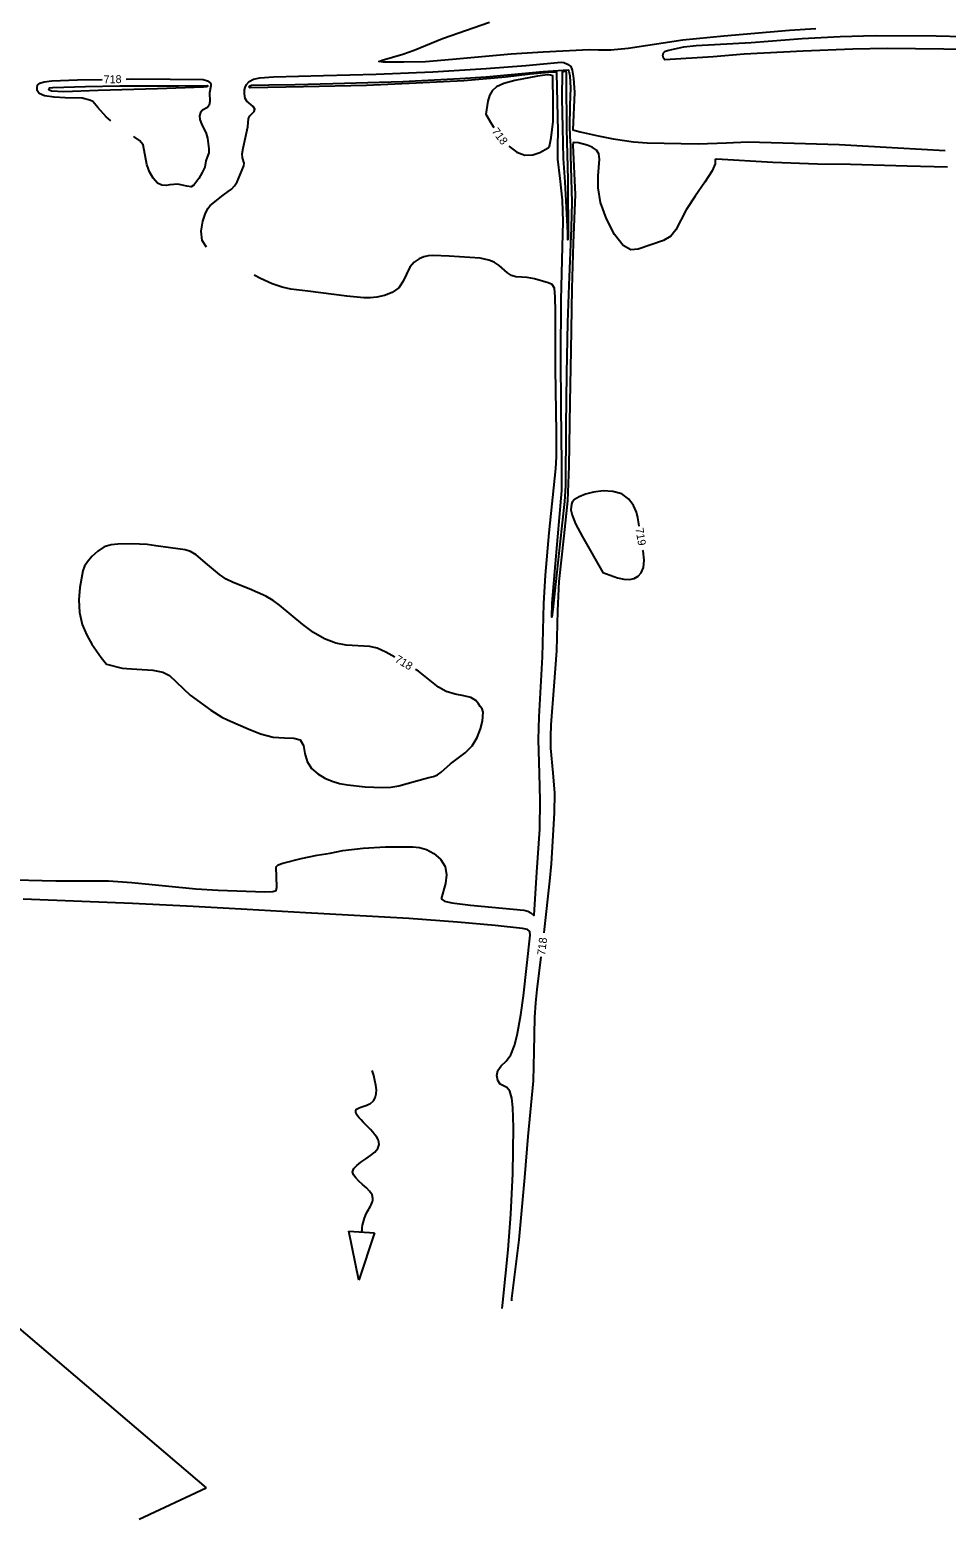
# Model space of a CAD drawing. Extents: x -310467766 to 17062430, y -322263100 to 8322522.
# Drawn here: x 1398127 to 1398585, y 573123 to 573867 of the extents above; entities that cross this region are included whole.
import ezdxf

# ---------------------------------------------------------------- set-up
doc = ezdxf.new("R2010")
doc.units = 0
for name, color, linetype in [('DT_X_Contour_Minor', 7, 'Continuous'), ('Level 19', 7, 'Continuous'), ('Level 40', 7, 'Continuous'), ('Level 56', 7, 'Continuous')]:
    doc.layers.add(name, color=color, linetype=linetype)

msp = doc.modelspace()

# ---------------------------------------------------------------- linework, layer by layer
at = {"layer": 'DT_X_Contour_Minor'}
for points in [[(1398520.21, 573867.55), (1398507.16, 573866.73), (1398474.35, 573863.99), (1398453.76, 573861.87), (1398426.53, 573857.74), (1398417.81, 573856.87), (1398411.71, 573856.95), (1398407, 573857.1), (1398384.02, 573855.93), (1398367.98, 573855), (1398338.64, 573852.19), (1398325.15, 573851.16), (1398314.44, 573850.86), (1398304.25, 573850.89), (1398301.93, 573851.25), (1398303.52, 573852.01), (1398313.79, 573854.88), (1398319.48, 573856.97), (1398333.67, 573862.81), (1398357.12, 573870.99)], [(1398615.85, 573856.83), (1398584.16, 573857.5), (1398555.98, 573857.84), (1398538.78, 573857.51), (1398513.89, 573856.48), (1398484.43, 573854.92), (1398468.93, 573853.68), (1398444.81, 573852.07), (1398444.12, 573852.99), (1398443.83, 573854.31), (1398444.16, 573855.54), (1398444.95, 573856.36), (1398446.79, 573856.96), (1398454.28, 573858.63), (1398460.49, 573859.2), (1398487.89, 573860.78), (1398513.51, 573862.76), (1398532.39, 573863.82), (1398549.96, 573864.24), (1398580.36, 573864.17), (1398607.44, 573863.5)], [(1398215.77, 573758.38), (1398213.52, 573761.79), (1398213.01, 573766.52), (1398213.91, 573771.41), (1398215.32, 573775.46), (1398216.52, 573777.95), (1398217.54, 573779.27), (1398224.15, 573784.5), (1398226.59, 573786.3), (1398228.21, 573787.45), (1398229.77, 573789.04), (1398231.07, 573791.16), (1398234.48, 573799.17), (1398234.65, 573800.43), (1398233.81, 573803.1), (1398233.6, 573805.16), (1398234.02, 573808.02), (1398236.45, 573818.54), (1398236.79, 573822.82), (1398237.4, 573824.05), (1398239.58, 573826.3), (1398239.9, 573827.47), (1398239.01, 573828.74), (1398235.95, 573831.44), (1398235.13, 573832.76), (1398234.81, 573835.11), (1398234.78, 573837.12), (1398235.05, 573838.3), (1398235.74, 573839.73), (1398237.07, 573841.19), (1398239.26, 573842.4), (1398242.39, 573843.14), (1398249.28, 573843.65), (1398274.26, 573844.27), (1398300.6, 573844.95), (1398328.91, 573846.09), (1398355.43, 573847.69), (1398375.27, 573849.35), (1398392.92, 573850.87), (1398394.39, 573850.74), (1398396.21, 573849.92), (1398397.75, 573848.79), (1398398.43, 573846.87), (1398399.08, 573842.88), (1398399.59, 573835.7), (1398398.74, 573817.18), (1398402.5, 573816.19), (1398411.4, 573814.03), (1398418.9, 573812.55), (1398429.18, 573811.16), (1398435.96, 573810.61), (1398461.49, 573810.1), (1398475.57, 573810.64), (1398486.3, 573811.05), (1398503.78, 573810.66), (1398531.95, 573809.73), (1398561.23, 573808.19), (1398584.86, 573806.78)], [(1398168.01, 573821.64), (1398165.68, 573823.6), (1398161.38, 573828.28), (1398158.9, 573831.31), (1398157.43, 573831.99), (1398153.65, 573832.86), (1398145.13, 573833.05), (1398139.54, 573833.39), (1398134.77, 573834.1), (1398132.08, 573835.28), (1398131.09, 573836.74), (1398131.04, 573838.2), (1398131.36, 573839.44), (1398132.38, 573840.42), (1398134.65, 573841.13), (1398138.48, 573841.59), (1398151.22, 573842.11), (1398163.6, 573842.31)], [(1398175.6, 573842.51), (1398178.45, 573842.56), (1398197.51, 573842.5), (1398214.05, 573842.24), (1398216.17, 573841.67), (1398217.59, 573840.58), (1398217.91, 573839.87), (1398217.96, 573839.09), (1398217.23, 573835.62), (1398217.39, 573831.23), (1398217.12, 573829.36), (1398216.26, 573828.25), (1398213.77, 573826.86), (1398212.8, 573825.7), (1398212.31, 573824.11), (1398212.45, 573822.2), (1398213.29, 573820.06), (1398215.6, 573815.34), (1398216.31, 573812.88), (1398216.9, 573807.56), (1398216.85, 573805.67), (1398216.1, 573803.42), (1398215.46, 573801.58), (1398214.97, 573798.49), (1398213.65, 573795.75), (1398211.96, 573792.73), (1398209.33, 573789.4), (1398208.03, 573788.67), (1398205.95, 573788.95), (1398201.4, 573790.03), (1398197.46, 573789.56), (1398195.57, 573789.3), (1398193.49, 573789.44), (1398191.31, 573790.52), (1398189.17, 573792.87), (1398187.31, 573796.15), (1398185.99, 573799.84), (1398184.05, 573809.57), (1398182.27, 573811.76), (1398179.65, 573813.65), (1398179.39, 573813.82)], [(1398260.09, 573839.84), (1398278.92, 573840.29), (1398313.92, 573841.33), (1398342.3, 573842.75), (1398355.45, 573843.65), (1398383.91, 573846.34), (1398396.47, 573847.15), (1398396.86, 573846.48), (1398397.28, 573844.04), (1398397.58, 573837.98), (1398397.37, 573829.47), (1398397.15, 573818.26), (1398397.5, 573810.79), (1398397.68, 573810.13), (1398397.57, 573804.27), (1398398.26, 573780.92), (1398398.05, 573768.2), (1398396.79, 573739.48), (1398396.21, 573720.86), (1398395.69, 573695.26), (1398395.26, 573669.04), (1398395.07, 573639.19), (1398394.67, 573631.34), (1398392.24, 573609.93), (1398388.76, 573577.25), (1398388.31, 573573.42), (1398388.44, 573580.54), (1398390.14, 573600.11), (1398393.32, 573636.85), (1398393.39, 573649.83), (1398392.91, 573678.72), (1398392.85, 573703.08), (1398393.04, 573731.99), (1398393.68, 573758.84), (1398394.01, 573771.09), (1398393.68, 573781.96), (1398392.51, 573792.71), (1398391.33, 573802.5), (1398391.34, 573809.36), (1398391.51, 573816.48), (1398390.9, 573845.52), (1398390.59, 573846.02), (1398388.59, 573845.97), (1398377.44, 573844.9), (1398365.09, 573843.51), (1398344.41, 573841.68), (1398320.51, 573840.45), (1398295.62, 573839.34), (1398264.18, 573838.56), (1398237.57, 573838.12), (1398237.14, 573838.45), (1398237.39, 573839.1), (1398238.2, 573839.36), (1398246.94, 573839.58), (1398260.09, 573839.84)], [(1398366.9, 573808.88), (1398370.8, 573805.94), (1398374.89, 573804.37), (1398378.87, 573804.55), (1398382.38, 573805.81), (1398386.51, 573808.14), (1398387.21, 573809), (1398388, 573813.13), (1398389.01, 573821.23), (1398389.04, 573830.34), (1398388.86, 573844.13), (1398387.63, 573844.51), (1398386.12, 573844.58), (1398381.19, 573843.88), (1398369.82, 573841.76), (1398364.33, 573840.28), (1398360.62, 573838.59), (1398358.45, 573836.62), (1398357.22, 573834.26), (1398356.42, 573831.51), (1398355.37, 573825), (1398358.1, 573820.18), (1398359.34, 573818.22)], [(1398395.43, 573845.94), (1398395.56, 573842.08), (1398395.6, 573817.42), (1398396.24, 573792.27), (1398396.54, 573762.21), (1398396.29, 573762.08), (1398396.27, 573765.66), (1398395, 573791.12), (1398394.23, 573802.83), (1398393.79, 573818.19), (1398393.44, 573832.98), (1398393.59, 573846.07), (1398394.9, 573846.41), (1398395.33, 573846.19), (1398395.43, 573845.94)], [(1398144.49, 573836.11), (1398138.22, 573836.45), (1398137, 573837.11), (1398137.05, 573837.78), (1398137.31, 573838.03), (1398138.95, 573838.32), (1398155.29, 573838.82), (1398172.35, 573839.11), (1398201.74, 573839.11), (1398216.25, 573839.23), (1398216.2, 573838.85), (1398215.8, 573838.58), (1398214.32, 573838.43), (1398191.33, 573837.62), (1398161.57, 573836.85), (1398144.49, 573836.11)], [(1398585.99, 573798.42), (1398565.84, 573798.96), (1398537.56, 573799.7), (1398521.08, 573799.89), (1398498.74, 573800.81), (1398470.69, 573802.51), (1398469.95, 573802.29), (1398470.03, 573801.72), (1398469.98, 573800.12), (1398468.51, 573796.69), (1398464.83, 573790.99), (1398459.99, 573784.03), (1398455.53, 573777.16), (1398450.35, 573767.13), (1398447.84, 573763.97), (1398444.19, 573761.82), (1398431.52, 573757.44), (1398427.86, 573757.09), (1398423.99, 573759.25), (1398419.68, 573764.81), (1398415.61, 573772.58), (1398412.67, 573780.84), (1398411.48, 573788.13), (1398411.54, 573794.17), (1398412.22, 573802.51), (1398411.83, 573805.09), (1398410.63, 573806.96), (1398408.53, 573808.37), (1398405.96, 573809.41), (1398401.59, 573810.58), (1398399.41, 573810.81), (1398398.97, 573810.55), (1398398.85, 573809.39), (1398400.03, 573784.85), (1398399.05, 573760.4), (1398398.25, 573737.74), (1398397.79, 573706.9), (1398397.36, 573680.85), (1398396.89, 573649), (1398396.07, 573631.6), (1398394.38, 573614.11), (1398391.87, 573591.33), (1398391.11, 573576.69), (1398390.63, 573556.65), (1398389.35, 573539.02), (1398387.82, 573519.67), (1398387.58, 573513.88), (1398387.65, 573508), (1398388.75, 573495.69), (1398389.63, 573485.57), (1398389.47, 573475.67), (1398388.02, 573450.22), (1398387.21, 573441.46), (1398384.49, 573417.4), (1398384.28, 573415.68)], [(1398333.1, 573432.62), (1398334.69, 573431.56), (1398338.34, 573430.73), (1398347.74, 573429.59), (1398374.29, 573427.1), (1398376.32, 573426.51), (1398377.77, 573425.63), (1398379.26, 573424.29), (1398379.5, 573424.6), (1398380.9, 573446.03), (1398382.27, 573467.54), (1398382.52, 573481.96), (1398382.19, 573495.2), (1398381.64, 573512.34), (1398381.96, 573523.63), (1398383.64, 573553.67), (1398384.31, 573580.32), (1398385.18, 573594.43), (1398386.97, 573615.59), (1398390.29, 573647.75), (1398390.64, 573653.65), (1398390.6, 573665.73), (1398390.1, 573697.71), (1398390.18, 573726.11), (1398390.03, 573733.68), (1398389.59, 573737.95), (1398388.55, 573739.77), (1398386.57, 573740.59), (1398379.74, 573742.62), (1398376.04, 573743.37), (1398370.3, 573743.69), (1398368.12, 573744.22), (1398366.17, 573745.57), (1398362.04, 573749.35), (1398359.46, 573750.9), (1398356.77, 573752.02), (1398352.43, 573753.01), (1398337.08, 573753.94), (1398328.83, 573754.37), (1398326.44, 573754.18), (1398324.35, 573753.62), (1398322, 573752.6), (1398319.57, 573750.94), (1398317.41, 573748.45), (1398314.04, 573741.4), (1398311.79, 573738.11), (1398308.55, 573735.79), (1398304.73, 573734.34), (1398300.94, 573733.53), (1398297.57, 573733.13), (1398294.29, 573733.1), (1398285.95, 573733.98), (1398266.39, 573736.54), (1398257.97, 573737.54), (1398253.56, 573738.46), (1398248.54, 573740.14), (1398242.76, 573742.75), (1398239.56, 573744.47)], [(1398431.94, 573618.91), (1398431.72, 573620.22), (1398431.37, 573623.11), (1398430.66, 573625.98), (1398429.17, 573629.27), (1398426.76, 573632.53), (1398423.31, 573635.07), (1398418.86, 573636.38), (1398413.92, 573636.59), (1398409.14, 573636.01), (1398405.07, 573634.92), (1398401.9, 573633.59), (1398399.72, 573632.24), (1398398.55, 573631.07), (1398398.08, 573629.97), (1398397.89, 573627.17), (1398398.44, 573624.56), (1398400.23, 573620.16), (1398403.59, 573613.66), (1398413.78, 573595.9), (1398421.12, 573593.21), (1398424.28, 573592.47), (1398427.08, 573592.33), (1398429.45, 573592.83), (1398431.43, 573593.96), (1398433.03, 573595.72), (1398434.09, 573598.3), (1398434.42, 573601.96), (1398433.94, 573606.73), (1398433.88, 573607.07)], [(1398309.93, 573553.47), (1398305.41, 573556.02), (1398301.1, 573557.98), (1398297.37, 573558.92), (1398285.46, 573559.53), (1398280.31, 573560.53), (1398274.79, 573562.59), (1398269.17, 573565.89), (1398263.83, 573569.85), (1398252.29, 573579.53), (1398249.07, 573581.8), (1398245.36, 573583.93), (1398237.09, 573587.69), (1398229.12, 573590.79), (1398225.5, 573592.57), (1398222.2, 573594.77), (1398216.21, 573599.91), (1398210.53, 573604.7), (1398207.79, 573606.3), (1398205.09, 573607.13), (1398190.46, 573609.21), (1398186.13, 573609.82), (1398178.5, 573610.1), (1398171.51, 573610.06), (1398168.06, 573609.72), (1398164.66, 573608.61), (1398161.38, 573606.47), (1398158.47, 573603.75), (1398156.24, 573601.12), (1398154.85, 573598.97), (1398154.02, 573596.68), (1398152.52, 573588.34), (1398151.97, 573582.23), (1398152.23, 573575.84), (1398153.66, 573569.88), (1398155.92, 573564.58), (1398158.51, 573560.01), (1398163.11, 573553.4), (1398165.82, 573550), (1398173.52, 573547.98), (1398178.33, 573547.66), (1398188.88, 573546.95), (1398193.87, 573545.96), (1398197.2, 573544.26), (1398207.66, 573534.55), (1398217.95, 573527.03), (1398223.41, 573523.44), (1398226.25, 573522.12), (1398231.53, 573519.87), (1398236.55, 573517.6), (1398242.66, 573515.18), (1398248.99, 573513.51), (1398254.74, 573513.12), (1398259.41, 573513.09), (1398262.61, 573512.14), (1398264.16, 573509.36), (1398264.93, 573505.4), (1398266.01, 573501.28), (1398268.22, 573497.82), (1398271.35, 573495.11), (1398274.92, 573493.04), (1398278.55, 573491.51), (1398282.29, 573490.42), (1398286.28, 573489.64), (1398295.11, 573488.73), (1398303.76, 573488.42), (1398307.83, 573488.6), (1398311.93, 573489.21), (1398320.22, 573491.59), (1398326.8, 573493.34), (1398329.17, 573493.84), (1398331.15, 573494.63), (1398332.97, 573496.03), (1398337.65, 573500.25), (1398344.96, 573505.67), (1398348.43, 573509.18), (1398350.99, 573513.38), (1398352.67, 573517.73), (1398353.63, 573521.55), (1398354.03, 573526.06), (1398353.48, 573527.62), (1398352.48, 573528.87), (1398351.67, 573530.25), (1398350.28, 573531.89), (1398347.89, 573533.31), (1398344.28, 573534.2), (1398339.95, 573535), (1398335.57, 573536.31), (1398331.69, 573538.56), (1398321.75, 573546.45), (1398320.25, 573547.34)], [(1398113.24, 573442.42), (1398140.46, 573441.73), (1398166.73, 573441.74), (1398178.42, 573440.94), (1398210.39, 573437.74), (1398221.59, 573437.11), (1398244.93, 573436.25), (1398248.94, 573436.31), (1398250.55, 573436.93), (1398250.85, 573438.49), (1398250.59, 573448.63), (1398251.51, 573449.68), (1398253.9, 573450.58), (1398263.13, 573452.94), (1398271.12, 573454.51), (1398277.49, 573455.59), (1398283.8, 573456.9), (1398293.96, 573458.08), (1398305.26, 573458.68), (1398318.8, 573458.72), (1398322.22, 573458.34), (1398325.67, 573457.31), (1398329.36, 573455.38), (1398332.74, 573452.55), (1398335.03, 573448.93), (1398335.7, 573444.69), (1398335.17, 573440.41), (1398333.1, 573432.62)], [(1398363.55, 573227.96), (1398363.88, 573230.92), (1398366.54, 573257.23), (1398367.81, 573275.03), (1398368.76, 573295.39), (1398369.23, 573318.41), (1398368.85, 573328.4), (1398368.29, 573333.1), (1398367.31, 573336.58), (1398365.85, 573338.35), (1398362.53, 573340.09), (1398361.29, 573341.93), (1398360.77, 573344.39), (1398361.3, 573346.92), (1398363.03, 573349.15), (1398365.45, 573351.55), (1398367.87, 573354.79), (1398369.72, 573359.3), (1398371.04, 573364.58), (1398372.81, 573374.65), (1398374.12, 573384.13), (1398377.46, 573414.55), (1398377.25, 573416.42), (1398376.15, 573417.32), (1398373.68, 573417.82), (1398359.96, 573419.44), (1398341.1, 573421.09), (1398316.81, 573422.89), (1398286.49, 573424.49), (1398265.26, 573425.71), (1398236.14, 573427.35), (1398209.12, 573428.8), (1398178.78, 573430.32), (1398153.5, 573431.43), (1398124.05, 573432.56)], [(1398382.86, 573403.76), (1398380.91, 573387.4), (1398380.19, 573380.75), (1398379.66, 573373.34), (1398379.25, 573356.41), (1398378.95, 573341.75), (1398376.35, 573313.96), (1398374.67, 573293.32), (1398371.76, 573262.21), (1398368.23, 573232.92), (1398368.14, 573231.71)]]:
    msp.add_lwpolyline(points, dxfattribs=at)
at = {"layer": 'Level 40'}
for p in [(1398079.01, 573254.6), (1398182.07, 573122.58)]:
    msp.add_line(p, (1398215.63, 573138.23), dxfattribs=at)
at = {"layer": 'Level 56'}
for p, q in [((1398291.79, 573242.14), (1398286.93, 573266.51)), ((1398286.93, 573266.51), (1398299.78, 573265.67)), ((1398299.78, 573265.67), (1398291.79, 573242.14))]:
    msp.add_line(p, q, dxfattribs=at)
msp.add_spline([(1398293.41, 573266.06), (1398293.47, 573267.01), (1398296.36, 573276.72), (1398298.93, 573282.82), (1398288.75, 573296.23), (1398302.05, 573309.95), (1398290.78, 573327.51), (1398297.69, 573330.47), (1398298.58, 573346.92)], degree=3, dxfattribs=at)

# ---------------------------------------------------------------- texts
at = {"layer": 'Level 19'}
for s, rotation, p in [('718', 0.95684, (1398164.39, 573840.33)), ('718', 306.84182, (1398358.08, 573816.33)), ('719', 279.32838, (1398430.08, 573617.85)), ('718', 329.27884, (1398309.56, 573551.37)), ('718', 83.20493, (1398384.94, 573404.28))]:
    msp.add_text(s, height=4, rotation=rotation, dxfattribs=at).set_placement(p)

doc.saveas('drawing.dxf')
